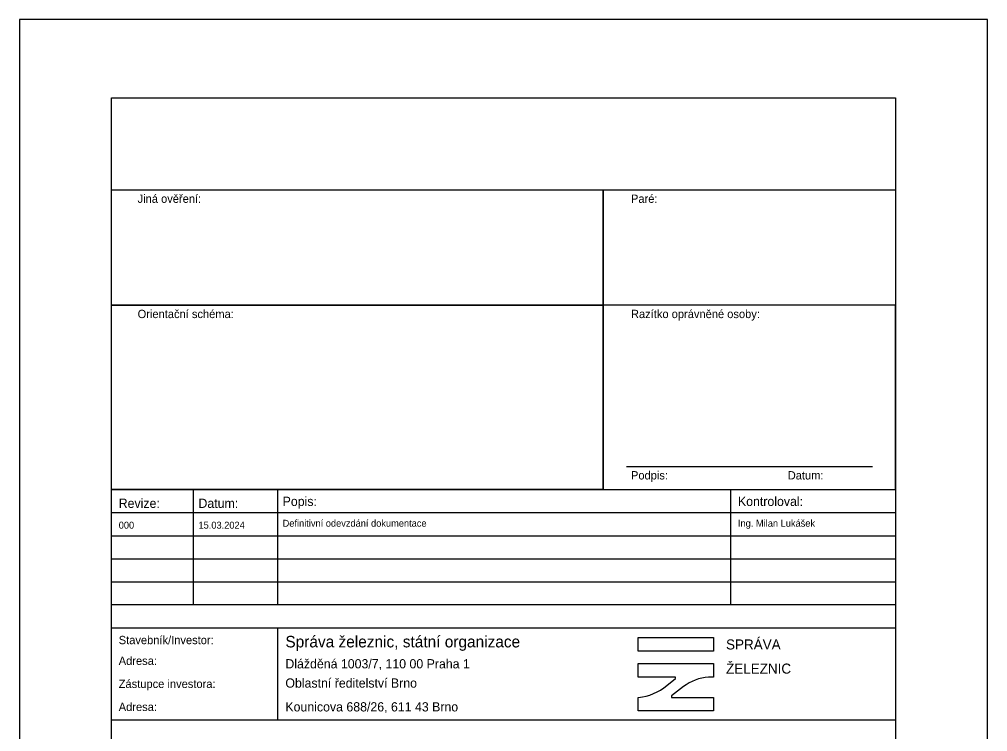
# Model space of a CAD drawing. Extents: x -97.1 to -76.1, y 399.9 to 429.6.
# Drawn here: x -97.06 to -76.06, y 414.2 to 429.65 of the extents above; entities that cross this region are included whole.
import ezdxf

# ---------------------------------------------------------------- set-up
doc = ezdxf.new("R2010")
doc.units = 0
for name, color, linetype in [('Default', 7, 'Continuous'), ('Rozpiska_Logo', 7, 'Continuous'), ('Rozpiska_pola_3', 7, 'Continuous'), ('Rozpiska_pole_1', 7, 'Continuous'), ('Rozpiska_pole_2', 7, 'Continuous'), ('Rozpiska_pole_4', 7, 'Continuous'), ('Rozpiska_pole_5', 7, 'Continuous'), ('Rozpiska_pole_6', 7, 'Continuous')]:
    doc.layers.add(name, color=color, linetype=linetype)

msp = doc.modelspace()

# ---------------------------------------------------------------- linework, layer by layer
at = {"layer": 'Default'}
for p, q in [((-76.063, 429.649), (-97.063, 429.649)), ((-97.063, 429.649), (-97.063, 399.949)), ((-76.063, 399.949), (-76.063, 429.649)), ((-84.398, 419.449), (-84.398, 425.949))]:
    msp.add_line(p, q, dxfattribs=at)
msp.add_lwpolyline([(-97.063, 399.949), (-76.063, 399.949), (-76.063, 429.649), (-97.063, 429.649)], close=True, dxfattribs=at)
at = {"layer": 'Rozpiska_Logo'}
for p, q in [((-82.829, 415.348), (-82.829, 415.383)), ((-83.023, 415.202), (-82.829, 415.348)), ((-82.66, 415.175), (-82.921, 414.973)), ((-82.921, 414.973), (-82.921, 414.942))]:
    msp.add_line(p, q, dxfattribs=at)
msp.add_lwpolyline([(-83.641, 416.24), (-82.011, 416.24), (-82.011, 415.947), (-83.641, 415.947)], close=True, dxfattribs=at)
for points in [[(-82.829, 415.383), (-83.641, 415.383), (-83.641, 415.676), (-82.011, 415.676), (-82.011, 415.383), (-82.118, 415.383)], [(-82.921, 414.942), (-82.011, 414.942), (-82.011, 414.649), (-83.641, 414.649), (-83.641, 414.942), (-83.634, 414.942)]]:
    msp.add_lwpolyline(points, dxfattribs=at)
for centre, radius, start, end in [((-82.044, 414.381), 1.004, 94.2142, 127.7808), ((-83.719, 415.991), 1.052, 274.6014, 311.4254)]:
    msp.add_arc(centre, radius, start, end, dxfattribs=at)
at = {"layer": 'Rozpiska_pola_3'}
msp.add_line((-83.898, 419.949), (-78.563, 419.949), dxfattribs=at)
at = {"layer": 'Rozpiska_pole_1'}
msp.add_lwpolyline([(-95.063, 427.949), (-78.063, 427.949), (-78.063, 401.449), (-95.063, 401.449)], close=True, dxfattribs=at)
at = {"layer": 'Rozpiska_pole_2'}
for points in [[(-95.063, 425.949), (-84.398, 425.949), (-84.398, 423.449), (-95.063, 423.449)], [(-84.398, 425.949), (-78.063, 425.949), (-78.063, 423.449), (-84.398, 423.449)], [(-95.063, 423.449), (-84.398, 423.449), (-84.398, 419.449), (-95.063, 419.449)], [(-78.063, 423.449), (-84.398, 423.449), (-84.398, 419.449), (-78.063, 419.449)]]:
    msp.add_lwpolyline(points, close=True, dxfattribs=at)
at = {"layer": 'Rozpiska_pole_4'}
for p, q in [((-93.285, 416.949), (-93.285, 419.449)), ((-91.458, 416.949), (-91.458, 419.449)), ((-81.633, 416.949), (-81.633, 419.449)), ((-95.063, 418.949), (-78.063, 418.949)), ((-95.063, 418.449), (-78.063, 418.449)), ((-95.063, 417.949), (-78.063, 417.949)), ((-95.063, 417.449), (-78.063, 417.449))]:
    msp.add_line(p, q, dxfattribs=at)
msp.add_lwpolyline([(-95.063, 419.449), (-78.063, 419.449), (-78.063, 416.949), (-95.063, 416.949)], close=True, dxfattribs=at)
at = {"layer": 'Rozpiska_pole_5'}
msp.add_line((-91.458, 414.449), (-91.458, 416.449), dxfattribs=at)
msp.add_lwpolyline([(-95.063, 416.449), (-78.063, 416.449), (-78.063, 414.449), (-95.063, 414.449)], close=True, dxfattribs=at)

# ---------------------------------------------------------------- texts
at = {"layer": 'Rozpiska_pola_3'}
for s, p in [('Paré:', (-83.798, 425.669)), ('Razítko oprávněné osoby:', (-83.798, 423.169)), ('Podpis:', (-83.798, 419.669)), ('Datum:', (-80.398, 419.669))]:
    msp.add_text(s, height=0.18, dxfattribs=at).set_placement(p)
at = {"layer": 'Rozpiska_pole_2'}
for s, p in [('Jiná ověření:', (-94.498, 425.669)), ('Orientační schéma:', (-94.498, 423.169))]:
    msp.add_text(s, height=0.18, dxfattribs=at).set_placement(p)
at = {"layer": 'Rozpiska_pole_4'}
for s, height, p in [('Revize:', 0.2, (-94.908, 419.052)), ('Datum:', 0.2, (-93.178, 419.052)), ('Popis:', 0.2, (-91.353, 419.094)), ('Kontroloval:', 0.2, (-81.478, 419.094)), ('000', 0.15, (-94.908, 418.602)), ('15.03.2024', 0.15, (-93.178, 418.602)), ('Definitivní odevzdání dokumentace', 0.15, (-91.353, 418.644)), ('Ing. Milan Lukášek', 0.15, (-81.478, 418.644))]:
    msp.add_text(s, height=height, dxfattribs=at).set_placement(p)
at = {"layer": 'Rozpiska_pole_5'}
for s, height, p in [('Stavebník/Investor:', 0.18, (-94.908, 416.096)), ('Správa železnic, státní organizace', 0.25, (-91.293, 416.026)), ('Adresa:', 0.18, (-94.908, 415.646)), ('Zástupce investora:', 0.18, (-94.908, 415.146)), ('Adresa:', 0.18, (-94.908, 414.646))]:
    msp.add_text(s, height=height, dxfattribs=at).set_placement(p)
at = {"layer": 'Rozpiska_pole_6'}
for s, height, p in [('SPRÁVA', 0.2183, (-81.736, 415.981)), ('Dlážděná 1003/7, 110 00 Praha 1', 0.2, (-91.293, 415.571)), ('ŽELEZNIC', 0.2183, (-81.736, 415.457)), ('Oblastní ředitelství Brno', 0.2, (-91.293, 415.153)), ('Kounicova 688/26, 611 43 Brno', 0.2, (-91.293, 414.637))]:
    msp.add_text(s, height=height, dxfattribs=at).set_placement(p)

doc.saveas('drawing.dxf')
